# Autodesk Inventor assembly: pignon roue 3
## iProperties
Author: Administrateur
Created: 2001-04
Part Number: pignon roue 3
Document SubType Name: Assemblage
Designer: Administrateur
Control State: 0
Master: False
Checked Out: False
PropertySet Name: Design Tracking Control
Shininess: 60.0
PropertySet Name: _Private Model Information
Length Units: 11269
Angle Units: 11283
Time Units: 11279
Mass Units: 11290
Length Display Precision: 3
Angle Display Precision: 2
Compacted: False
Density: 0.0
Volumn: 0.0
Area: 0.0
PropertySet Name: Model Information
